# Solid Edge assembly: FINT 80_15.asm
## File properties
Title: Zylinder
Author: bmolnar
Template: iso assembly.asm
Last saved by: bmolnar
Revision: 11
Application: Solid Edge
Username: bmolnar
Dokumentum tartalom típus: 1
Document Number: FINT 80/15
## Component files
Kit_1.par
Kolbenstange.par
Kit_2.par
Profilrohr.par
Platte.par
hrungsstange.par
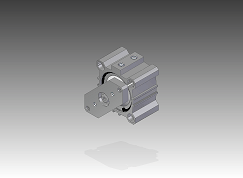
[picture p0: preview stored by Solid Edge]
